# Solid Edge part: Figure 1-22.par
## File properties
Author: Lenovo i5
Template: iso metric part.par
Last saved by: Lenovo i5
Revision: 1
Application: Solid Edge
Density: 7750,000 kg/m^3
Accuracy: 0,990
Username: Lenovo i5
Material: Stainless Steel, 420
Face Style: Steel
Fill Style: ANSI32(Steel)
Virtual Style: Stainless steel
Grouping: Metals\Steel
LibraryName: Materials
Coef. of Thermal Exp: 1e-05
Thermal Conductivity: 25.0
Specific Heat: 502.0
Modulus of Elasticity: 199947953000.0
Poisson's Ratio: 0.29
Yield Stress: 344737850.0
Ultimate Stress: 655001915.0
Elongation: 0.0
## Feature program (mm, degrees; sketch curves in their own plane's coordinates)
fearecompute load "unnamed FEARecomputeLoad 1"
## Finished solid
Body 1: solid body, 10 faces, 24 edges, 16 vertices.
  Faces by surface: plane 10
  Edges by curve: line 24
Bounding box of the edges (mm): 1200.000 x 200.000 x 1000.000, from (-100, -100, 0) to (1100, 100, 1000).
Planar faces by outward normal: +x 3, +y 1, +z 2, -x 1, -y 1, -z 2
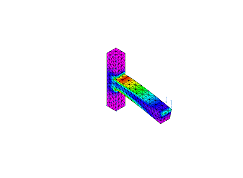
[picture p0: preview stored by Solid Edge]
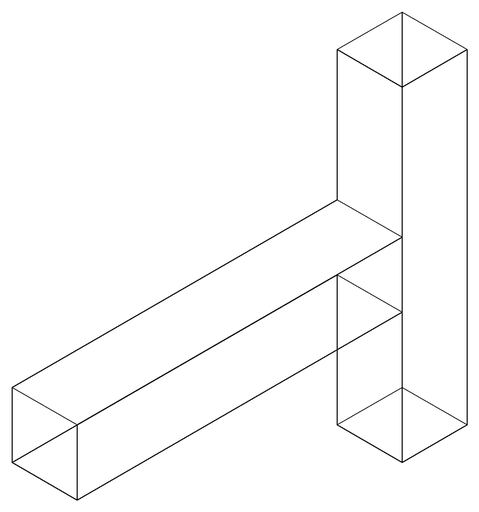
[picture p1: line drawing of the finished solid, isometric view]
